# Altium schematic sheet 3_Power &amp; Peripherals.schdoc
size 307 x 218 mm; Symbol: Artery_A4; Device: Artery_A4; @Project Name: AT-START-M416; @Page Count: 4; @Create Date: 2024-11-11; Company: Artery Technology; Drawed: SD; Version: 1.1; Page Size: A4; @Update Date: 2024-12-31; @Page No: 3; @Schematic Name: AT-START-M416-V1.1; @Page Name: Power &amp; Peripherals; Title Block Position: 3; Width: 1170; Height: 825; Region Start: 1; X Region Count: 6; Y Region Count: 4; Blade Width: 10; @Board Name: AT-START-M416-V1.1; @Create Time: 14:16:05; @Update Time: 17:37:59
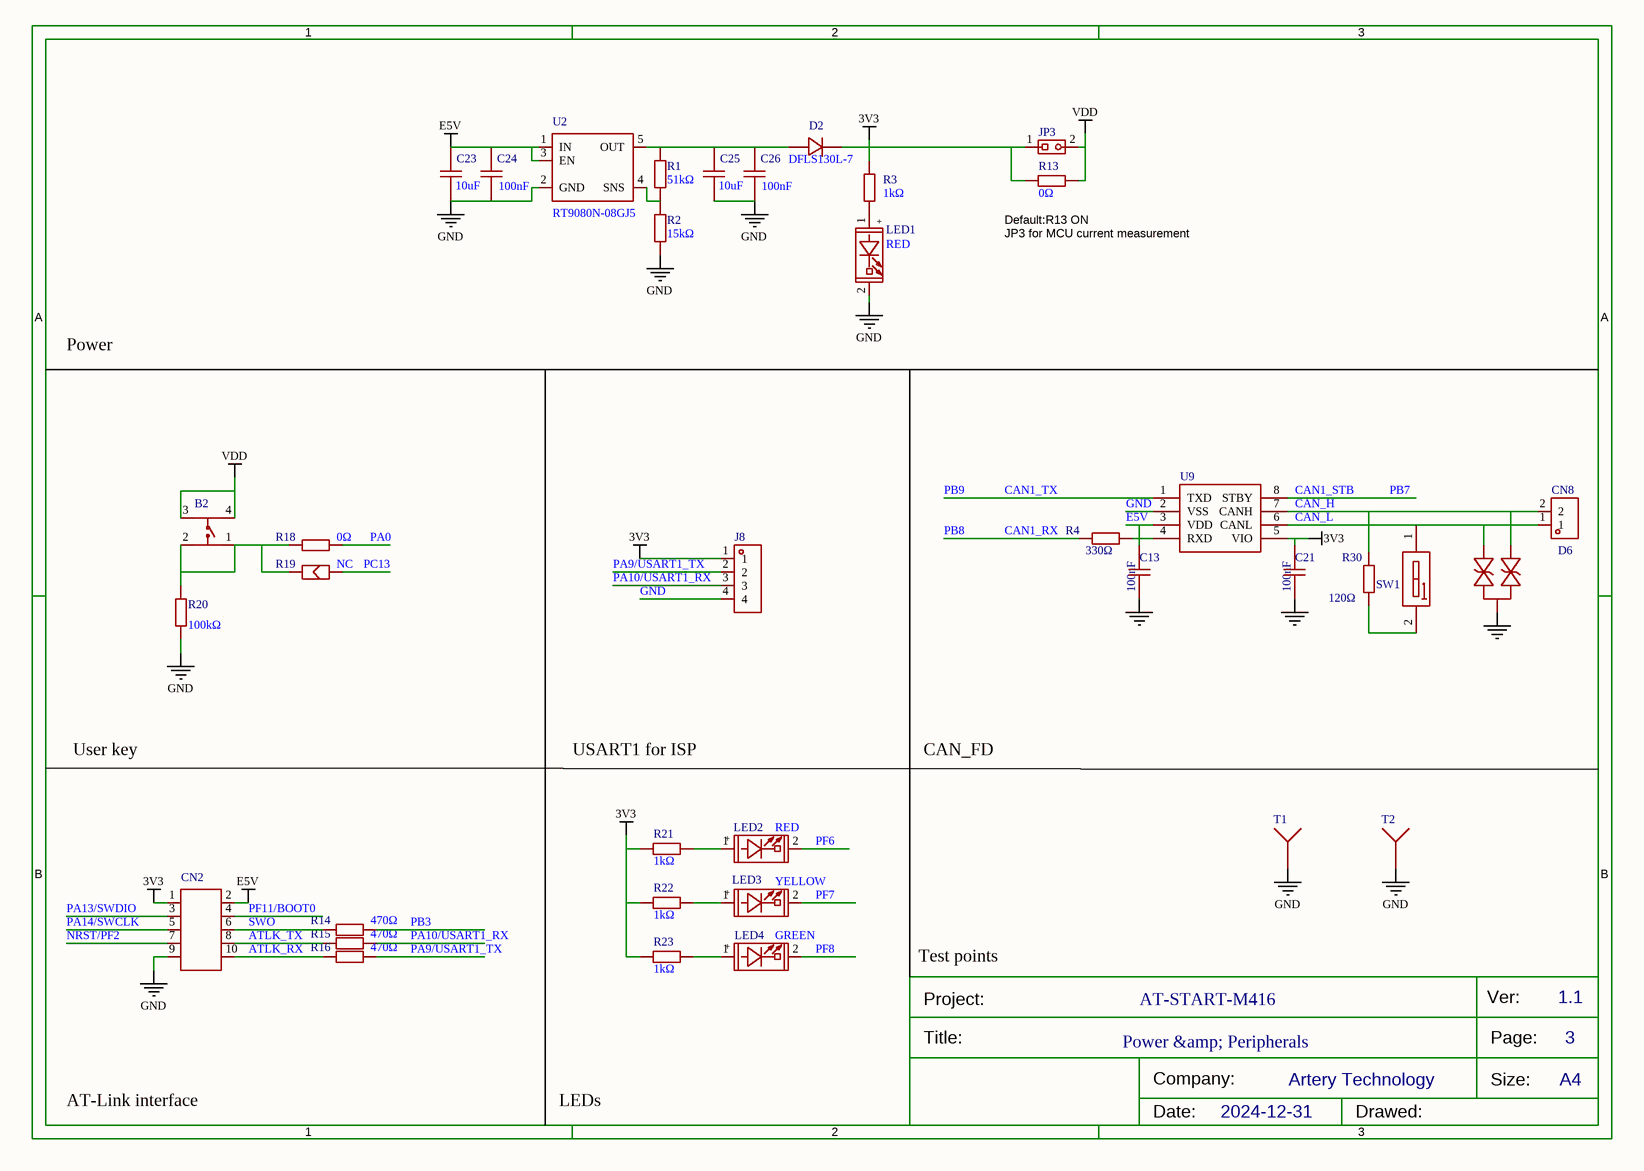
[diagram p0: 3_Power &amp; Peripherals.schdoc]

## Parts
B2  TSA063G60-250  [KEY-SMD_4P-L6.1-W6.1-P4.50-LS9.0]  (value not drawn)
C13  100nF  [C0603]
C21  100nF  [C0603]
C23  10uF  [C0603]
C24  100nF  [C0603]
C25  10uF  [C0603]
C26  100nF  [C0603]
CN2  CON10  [HDR2X5]  (value not drawn)
CN8  KF301-5.0-2P  [CONN-TH_P5.00_KF301-5.0-2P]  (value not drawn)
D2  DFLS130L-7  [POWERDI-123_L2.8-W1.8-LS3.7-RD]
D6  PESD2CANFD24V-TR  [SOT-23-3_L2.9-W1.3-P1.90-LS2.4-BR]  (value not drawn)
J8  PZ2.54-1*4-WZ  [HDR-TH_4P-P2.54-H-M-W7.7-P]  (value not drawn)
JP3  1X2P_2.54M  [HDR1X2]  (value not drawn)
LED1  RED  [LED0603]
LED2  RED  [LED0603]
LED3  YELLOW  [LED0603]
LED4  GREEN  [LED0603]
R1  51kΩ  [R0603]
R2  15kΩ  [R0603]
R3  1kΩ  [R0603]
R4  330Ω  [R0603]
R13  0Ω  [SB-PAD_2]
R14  470Ω  [R0603]
R15  470Ω  [R0603]
R16  470Ω  [R0603]
R18  0Ω  [SB-PAD_2]
R19  NC  [SB-PAD_2]
R20  100kΩ  [R0603]
R21  1kΩ  [R0603]
R22  1kΩ  [R0603]
R23  1kΩ  [R0603]
R30  120Ω  [R0603]
SW1  DSWB01LHGET  [SW-TH_DSWB01LHGET]  (value not drawn)
T1  Test point  [TestPoint]  (value not drawn)
T2  Test point  [TestPoint]  (value not drawn)
U2  RT9080N-08GJ5  [SOT-23-5]
U9  MCP2562FD-E/SN  [SOIC-8_L4.9-W3.9-P1.27-LS6.0-BL]  (value not drawn)

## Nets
3V3: C21.2 CN2.1 D2.1 J8.1 JP3.1 R3.2 R13.2 R21.2 R22.2 R23.2 U9.5(VIO)
E5V: C13.2 C23.1 C24.1 CN2.2 U2.1(IN) U2.3(EN) U9.3(VDD)
GND: C13.1 C21.1 C23.2 C24.2 C25.2 C26.2 CN2.9 D6.3 J8.4 LED1.2(CATHODE) R2.2 R20.2 T1.1 T2.1 U2.2(GND) U9.2(VSS)
VDD: B2.3 B2.4 JP3.2 R13.1
ATLK_RX: CN2.10 R16.2
ATLK_TX: CN2.8 R15.2
CAN1_RX: R4.1  [also labelled PB8]
CAN1_STB: U9.8(STBY)  [also labelled PB7]
CAN1_TX: U9.1(TXD)  [also labelled PB9]
CAN_H: CN8.2 D6.1 R30.2 U9.7(CANH)
CAN_L: CN8.1 D6.2 SW1.1(A1) U9.6(CANL)
NRST/PF2: CN2.7
PA0: R18.1
PA9/USART1_TX: J8.2 R16.1
PA10/USART1_RX: J8.3 R15.1
PA13/SWDIO: CN2.3
PA14/SWCLK: CN2.5
PB3: R14.1
PC13: R19.1
PF6: LED2.2(CATHODE)
PF7: LED3.2(CATHODE)
PF8: LED4.2(CATHODE)
PF11/BOOT0: CN2.4
SWO: CN2.6 R14.2
NetB2_1: B2.1 B2.2 R18.2 R19.2 R20.1
NetC25_1: C25.1 C26.1 D2.2 R1.1 U2.5(OUT)
NetLED1_1: LED1.1(ANODE) R3.1
NetLED2_1: LED2.1(ANODE) R21.1
NetLED3_1: LED3.1(ANODE) R22.1
NetLED4_1: LED4.1(ANODE) R23.1
NetR1_2: R1.2 R2.1 U2.4(SNS)
NetR4_2: R4.2 U9.4(RXD)
NetR30_1: R30.1 SW1.2

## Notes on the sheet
- (near R13) JP3 for MCU current measurement
- (near R13) Default:R13 ON
- Power
- User key
- USART1 for ISP
- CAN_FD
- Test points
- AT-START-M416
- AT-Link interface
- LEDs

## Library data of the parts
B2 = TSA063G60-250: Manufacturer: BRIGHT(博瑞泰); Add into BOM: yes; Circuit: 单刀单掷; Actuator Style: 圆形按钮; Operating Force: 250gf; Switch Length: 6.1mm; Switch Height: 6mm; Strike Gundam: 不带; Contact Current: 50mA; Voltage Rating (DC): 12V; Insulation Resistance: 100MΩ; Actuator/Cap Color: 黑色; With Lamp: 无; Pin Style: 鸥翼型; Mechanical Life: 5万次; Origin Footprint: KEY_SOP_6*6
C13 C21 = CC0603KRX7R9BB104: Manufacturer: YAGEO(国巨); Add into BOM: yes; Tolerance: ±10%; Voltage Rated: 50V; Temperature Coefficient: X7R
C23 C25 = CL10A106KP8NNNC: Manufacturer: SAMSUNG(三星); Add into BOM: yes; Tolerance: ±10%; Voltage Rated: 10V; Temperature Coefficient: X5R; Origin Footprint: 0603_C-M
C24 C26 = CC0603KRX7R9BB104: Manufacturer: YAGEO(国巨); Add into BOM: yes; Tolerance: ±10%; Voltage Rated: 50V; Temperature Coefficient: X7R; Origin Footprint: 0603_C-M
CN2 = CON10: Symbol: CON10A_0; Add into BOM: yes
CN8 = KF301-5.0-2P: Manufacturer: KEFA(科发); Add into BOM: yes; Structure: 1x2P; Pitch: 5mm; Current Rating (Max): 17A; Voltage Rating (Max): 250V; Wire Gauge - AWG: 14~22; Wire Gauge - mm2: 1.5; Number of PINs Per Row: 2
D2 = DFLS130L-7: Manufacturer: DIODES(美台); Add into BOM: yes; Forward Voltage (Vf@If): 310mV@1A; Reverse Voltage (Vr): 30V; Average Rectified Current (Io): 1A; Origin Footprint: SOD-123
D6 = PESD2CANFD24V-TR: Manufacturer: Nexperia(安世); Add into BOM: yes; Reverse Stand-Off Voltage (Vrwm): 24V; Maximum Clamping Voltage: 42V; Breakdown Voltage: 25.5V; Type: ESD
J8 = PZ2.54-1*4-WZ: Manufacturer: ZHOURI(洲日); Add into BOM: yes; Pin Structure: 1x4P; Pitch: 2.54mm; Origin Footprint: HDR1X4
JP3 = 1X2P_2.54M: Symbol: 1X2P,Male,DIP_2.54; Origin Footprint 2: SIP_2P; Add into BOM: yes; Check: true
LED1 LED2 = RED: Symbol: RED,SMD0603; Add into BOM: yes
LED3 = YELLOW: Symbol: YELLOW,SMD0603; Add into BOM: yes
LED4 = GREEN: Symbol: GREEN,SMD0603; Add into BOM: yes
R1 = 0603WAF5102T5E: Manufacturer: UNI-ROYAL(厚声); Add into BOM: yes; Tolerance: ±1%; Power(Watts): 100mW; Overload Voltage (Max): 75V; Temperature Coefficient: ±100ppm/℃
R2 = 0603WAF1502T5E: Manufacturer: UNI-ROYAL(厚声); Add into BOM: yes; Tolerance: ±1%; Power(Watts): 100mW; Overload Voltage (Max): 75V; Temperature Coefficient: ±100ppm/℃
R3 R21-R23 = 0603WAF1001T5E: Manufacturer: UNI-ROYAL(厚声); Add into BOM: yes; Tolerance: ±1%; Power(Watts): 100mW; Overload Voltage (Max): 75V; Temperature Coefficient: ±100ppm/℃
R4 = 0603WAF3300T5E: Manufacturer: UNI-ROYAL(厚声); Add into BOM: yes; Tolerance: ±1%; Power(Watts): 100mW; Overload Voltage (Max): 75V; Temperature Coefficient: ±100ppm/℃
R13 R18 = 0603WAF0000T5E: Manufacturer: UNI-ROYAL(厚声); Add into BOM: yes; Tolerance: ±1%; Power(Watts): 100mW; Overload Voltage (Max): 75V; Origin Footprint: SB-PAD
R14-R16 = 0603WAF4700T5E: Manufacturer: UNI-ROYAL(厚声); Add into BOM: yes; Tolerance: ±1%; Power(Watts): 100mW; Overload Voltage (Max): 75V; Temperature Coefficient: ±100ppm/℃; Origin Footprint: 0603_R-M
R19 = SB_PAD: Symbol: SB-PAD; Convert to PCB: yes
R20 = 0603WAF1003T5E: Manufacturer: UNI-ROYAL(厚声); Add into BOM: yes; Tolerance: ±1%; Power(Watts): 100mW; Overload Voltage (Max): 75V; Temperature Coefficient: ±100ppm/℃
R30 = 0603WAF1200T5E: Manufacturer: UNI-ROYAL(厚声); Add into BOM: yes; Tolerance: ±1%; Power(Watts): 100mW; Overload Voltage (Max): 75V; Temperature Coefficient: ±100ppm/℃
SW1 = DSWB01LHGET: Manufacturer: YE; Add into BOM: yes; Circuit: 单刀单掷; Number of Positions: 1位
T1 T2 = Test point: Symbol: Socket; Add into BOM: yes
U2 = RT9080N-08GJ5: Add into BOM: yes
U9 = MCP2562FD-E/SN: Manufacturer: MICROCHIP(美国微芯); Add into BOM: yes; Data Rate: 8Mbps; Supply Voltage: 4.5V~5.5V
